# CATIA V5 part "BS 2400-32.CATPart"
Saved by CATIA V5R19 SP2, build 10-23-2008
Part number: BS 2400-32
Bounding box of the stored display mesh (mm): x -37.351 to 37.351, y -37.351 to 37.351, z 0 to 109
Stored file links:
  C:\Users\Bora\Desktop\3D Katı model\BS serisi\BS 2400\BS 2400-32.CATPart
  C:\Program Files\Dassault Systemes\B19\intel_a\reffiles\standard\MetricThickPitch.txt
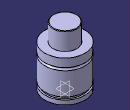
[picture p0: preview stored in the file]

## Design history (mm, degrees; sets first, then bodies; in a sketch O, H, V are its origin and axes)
Body1 (main body)
  Sketch1 on yz-plane, origin (0, 0, 0), H (0, 1, 0), V (0, 0, 1)
    point P1 (22.5, 108)
    point P3 (22.5, 108)
    point P7 (37.5, 60.5)
    point P9 (37.5, 60.5)
    point P10 (37.5, 55.5)
    point P14 (37.5, 55.5)
    line L1 (22.5, 108) -> (22.5, 76)
    arc A1 centre (21.5, 108) radius 1 from (22.5, 108) to (21.5, 109) ccw
    line L2 (37.5, 0) -> (37.5, 8)
    line L3 (37.5, 60.5) -> (37.5, 76)
    arc A2 centre (37.5, 58) radius 2.5 from (37.5, 60.5) to (37.5, 55.5) ccw
    line L4 (34.5, 13) -> (34.5, 8)
    line L5 (37.5, 13) -> (37.5, 55.5)
    line L6 (21.5, 109) -> (0, 109)
    point P15 (0, 109)
    line L7 (22.5, 76) -> (37.5, 76)
    line L8 (34.5, 13) -> (37.5, 13)
    line L9 (34.5, 8) -> (37.5, 8)
    line L10 (0, 0) -> (37.5, 0)
    coincidence: P15 V, P1 P3, P7 P9, P10 P14
    tangency: L6 A1
    horizontal: L7 H, L8 H, L9 H, L10 H
  Shaft1: profile Sketch1, axis Sketch1.V, angle 360
  Sketch2 on face of Shaft1 from Sketch1.L10, origin (0, 0, 0), H (1, 0, 0), V (0, -1, 0)
    point P1 (20, 0)
    distance P1 V = 20
  Hole1: placed by Sketch2, at (20, 0, 0) direction (0, 0, 1), diameter 6.647, depth 5, threaded "M8", thread diameter 8, thread depth 5, pitch 1.25
  CircPattern1: of Hole1, instances 4, angular step 90, axis from xy-plane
